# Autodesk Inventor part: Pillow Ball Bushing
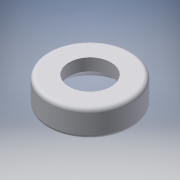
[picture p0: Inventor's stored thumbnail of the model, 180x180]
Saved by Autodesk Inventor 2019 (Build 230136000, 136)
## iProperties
Shininess: 50.0
Compacted: True
Length Units: 11272
Angle Units: 11279
Time Units: 11290
Mass Units: 11286
Length Display Precision: 4
Angle Display Precision: 2
Company: Autodesk
Created: 2000-05
Part Number: Pillow Ball Bushing
Project: Inventor Samples
User Status: IN PROGRESS
Document SubType Name: Modeling
Designer: Autodesk, Inc.
Density: 8.08 g/cm^3
Material: Stainless Steel
Mass: 0.67634 g
Surface Area: 1.66253 cm^2
Volume: 0.0837055 cm^3
Appearance: Light Grey
Density: 0.0
Volumn: 0.0
Area: 0.0
PropertySet Name: Model Information
Control State: 0
Master: False
Checked Out: False
Checked Out Date: 2018-05-30
Last Check In Date: 2018-05-30
Author: Autodesk, Inc.
Revision Number: A
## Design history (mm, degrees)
node "Revolution1" dims "d2" = 90 deg
  sketch "Sketch2"
    geometry: L1 (-22.433, 12.899)-(-14.178, 12.899); L2 (-14.178, 12.899)-(-14.178, 8.136); L3 (-22.433, 8.136)-(-22.433, 8.136); L4 (-18.306, 8.136)-(-18.306, 12.899); A1 r 4.128 centre (-18.306, 8.136) between (-14.178, 8.136) and (-18.306, 12.264)
    constraints: 8 end point, 3 point on circle, 2 horizontal alignment, 2 parallel, 1 centre point, 1 coincident, 1 horizontal, 1 midpoint, 1 perpendicular, 1 point on line, 1 other
    dimensions: "d0" = 0.635 distance edge to line of A1 L1; "d1" = 8.255 diameter of A1
node "Fillet1" dims "d3" = 0.381, "d4" = 0.381
node "Extrusion1" dims "d6" = 25.4, "d7" = 0
  sketch "Sketch3"
    geometry: C1 r 3.746 at (0, 0) reference; C2 r 2.064 at (0, 0)
    constraints: 1 centre point, 1 coincident
    dimensions: "d5" = 4.1275 diameter of C2
body "Solid1"
